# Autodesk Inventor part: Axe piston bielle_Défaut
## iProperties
Shininess: 64.0
Length Units: 11269
Angle Units: 11279
Time Units: 11290
Mass Units: 11283
Length Display Precision: 3
Angle Display Precision: 2
Compacted: True
Part Number: Axe piston bielle_Défaut
Document SubType Name: Modeling
Created: 2006-01
Material: Par défaut
Designer: riri
Density: 0.0
Volumn: 0.0
Area: 0.0
PropertySet Name: Model Information
Control State: 0
Master: False
Checked Out: False
Author: riri
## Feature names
1. Base1
